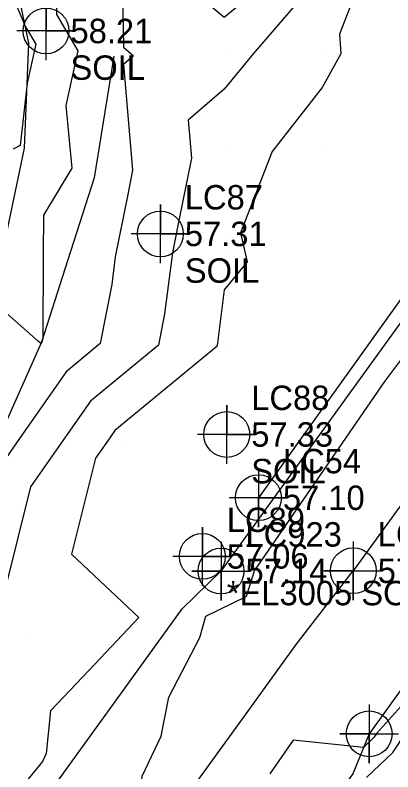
# Model space of a CAD drawing. Extents: x 2188792 to 2191981, y 386090 to 389710.
# Drawn here: x 2189598.9 to 2189637.5, y 386896.6 to 386974.1 of the extents above; entities that cross this region are included whole.
import ezdxf

# ---------------------------------------------------------------- set-up
doc = ezdxf.new("R2010")
doc.units = 0
for name, color, linetype in [('DTM Contours Major', 7, 'Continuous'), ('DTM Contours Minor', 7, 'Continuous'), ('Exist DTM QL2 LIDAR Elevation Point', 7, 'Continuous'), ('Exist Roads EOP', 7, 'Continuous'), ('Exist Roads EOP Cogo Elevation', 7, 'Continuous'), ('Exist Roads EOP Cogo Number', 7, 'Continuous'), ('Exist Roads EOP Cogo Point CELL', 7, 'Continuous'), ('Exist Roads EOT', 7, 'Continuous'), ('Exist Roads EOT Cogo Elevation', 7, 'Continuous'), ('Exist Roads EOT Cogo Number', 7, 'Continuous'), ('Exist Roads EOT Cogo Point CELL', 7, 'Continuous'), ('Exist Roads Soil Cogo Comment', 7, 'Continuous'), ('Exist Roads Soil Cogo Elevation', 7, 'Continuous'), ('Exist Roads Soil Cogo Number', 7, 'Continuous'), ('Exist Roads Soil Cogo Point CELL', 7, 'Continuous'), ('PH Exist DTM Breakline', 7, 'Continuous')]:
    doc.layers.add(name, color=color, linetype=linetype)

msp = doc.modelspace()

# ---------------------------------------------------------------- linework, layer by layer
at = {"layer": 'DTM Contours Major'}
for points in [[(2189634.793, 386896.032), (2189637.473, 386898.6), (2189638.925, 386900.819), (2189644.833, 386907.402), (2189646.214, 386909.493), (2189656.034, 386923.273), (2189657.363, 386925.28), (2189658.603, 386926.878), (2189659.963, 386928.63), (2189661.46, 386930.56), (2189674.176, 386948.424), (2189675.489, 386950.089), (2189676.955, 386951.946), (2189678.6, 386954.032), (2189687.057, 386966.203), (2189688.644, 386968.279), (2189690.321, 386970.473), (2189702.993, 386988.788)], [(2189598.458, 386976.342), (2189599.911, 386972.861), (2189600.962, 386971.086), (2189600.085, 386967.099), (2189599.372, 386960.714), (2189598.635, 386960.347)]]:
    msp.add_lwpolyline(points, dxfattribs=at)
at = {"layer": 'DTM Contours Minor'}
for points in [[(2189601.657, 387036.604), (2189618.405, 387013.751), (2189616.243, 386991.995), (2189616.527, 386990.987), (2189630.888, 386980.036), (2189630.229, 386978.331), (2189623.177, 386970.118), (2189620.228, 386966.506), (2189616.533, 386963.306), (2189616.87, 386959.434), (2189615.516, 386952.703), (2189614.928, 386949.749), (2189614.132, 386943.507), (2189613.507, 386940.291), (2189606.553, 386934.556), (2189603.995, 386930.889), (2189600.424, 386925.77), (2189597.718, 386914.935)], [(2189593.055, 387031.078), (2189600.943, 387033.286), (2189614.438, 387014.872), (2189612.991, 387000.305), (2189605.127, 386996.816), (2189608.731, 386989.594), (2189609.618, 386985.949), (2189609.81, 386978.627), (2189609.937, 386970.781), (2189610.963, 386969.912), (2189609.922, 386969.011), (2189610.862, 386958.212), (2189610.327, 386955.551), (2189609.091, 386949.344), (2189608.729, 386946.512), (2189607.551, 386940.447), (2189604.061, 386937.568), (2189599.768, 386931.415), (2189593.775, 386922.823)], [(2189594.519, 387001.065), (2189601.128, 386987.823), (2189602.944, 386980.358), (2189603.015, 386977.654), (2189603.072, 386974.14), (2189605.269, 386970.427), (2189604.037, 386964.824), (2189604.651, 386958.391), (2189601.761, 386953.606), (2189601.732, 386949.645), (2189601.666, 386940.969), (2189601.595, 386940.603), (2189601.568, 386940.581), (2189601.488, 386940.465), (2189601.205, 386940.706), (2189595.646, 386945.562)], [(2189616.322, 386990.396), (2189627.871, 386980.119), (2189620.228, 386973.839), (2189616.649, 386976.871), (2189616.604, 386979.6), (2189616.322, 386990.396)], [(2189634.896, 386979.534), (2189632.03, 386972.124), (2189632.158, 386970.118), (2189630.229, 386966.656), (2189625.118, 386960.117), (2189621.893, 386951.781), (2189622.589, 386948.802), (2189620.228, 386945.942), (2189619.534, 386940.501), (2189619.463, 386940.135), (2189609.045, 386931.544), (2189608.222, 386930.364), (2189607.073, 386928.716), (2189604.622, 386918.903), (2189611.512, 386912.406), (2189606.427, 386907.029), (2189602.475, 386902.85), (2189602.034, 386898.501), (2189601.65, 386897.677), (2189596.041, 386890.809)], [(2189595.706, 386865.733), (2189600.685, 386873.259), (2189600.927, 386873.579), (2189605.77, 386880.868), (2189606.162, 386881.389), (2189610.879, 386888.463), (2189611.275, 386889.439), (2189611.832, 386896.164), (2189613.77, 386900.277), (2189614.569, 386904.247), (2189617.719, 386910.372), (2189618.334, 386912.55), (2189622.467, 386914.577), (2189622.522, 386914.604), (2189623.321, 386917.175), (2189636.667, 386936.578), (2189639.311, 386940.124), (2189649.551, 386955.072), (2189652.538, 386959.069), (2189666.8, 386977.462)], [(2189690.18, 386977.049), (2189683.33, 386965.967), (2189675.62, 386954.246), (2189674.072, 386952.019), (2189674.041, 386951.979), (2189674.013, 386951.943), (2189673.988, 386951.911), (2189656.935, 386927.955), (2189656.782, 386927.758), (2189656.643, 386927.579), (2189656.516, 386927.415), (2189656.38, 386927.21), (2189643.714, 386909.437), (2189643.499, 386909.111), (2189635.829, 386900.566), (2189635.537, 386900.119), (2189634.487, 386899.114), (2189627.293, 386899.84), (2189624.901, 386896.425)]]:
    msp.add_lwpolyline(points, dxfattribs=at)
at = {"layer": 'Exist DTM QL2 LIDAR Elevation Point'}
for p, q in [((2189620.228, 386970.118), (2189620.228, 386970.118)), ((2189630.229, 386970.118), (2189630.229, 386970.118)), ((2189620.228, 386960.117), (2189620.228, 386960.117)), ((2189630.229, 386960.117), (2189630.229, 386960.117)), ((2189620.228, 386950.116), (2189620.228, 386950.116)), ((2189620.228, 386940.115), (2189620.228, 386940.115)), ((2189610.227, 386930.114), (2189610.227, 386930.114)), ((2189600.226, 386910.112), (2189600.226, 386910.112))]:
    msp.add_line(p, q, dxfattribs=at)
at = {"layer": 'Exist Roads EOP'}
msp.add_lwpolyline([(2190313.986, 387884.141), (2190285.547, 387843.636), (2190254.588, 387800.045), (2190225.155, 387759.32), (2190194.829, 387717.425), (2190164.291, 387675.101), (2190137.229, 387637.301), (2190105.098, 387592.774), (2190071.411, 387546.221), (2190039.296, 387501.568), (2190007.542, 387457.958), (2189976.844, 387415.407), (2189936.359, 387359.145), (2189907.138, 387318.716), (2189868.636, 387265.243), (2189836.428, 387220.463), (2189805.695, 387177.815), (2189775.592, 387135.957), (2189745.498, 387094.055), (2189715.496, 387052.249), (2189683.869, 387008.07), (2189653.218, 386965.867), (2189623.729, 386924.667)], dxfattribs=at)
at = {"layer": 'Exist Roads EOP Cogo Point CELL'}
msp.add_lwpolyline([(2189623.729, 386927.667), (2189623.729, 386921.667), (2189623.729, 386924.667), (2189626.729, 386924.667), (2189620.729, 386924.667)], dxfattribs=at)
msp.add_circle((2189623.729, 386924.667), 2.344, dxfattribs=at)
at = {"layer": 'Exist Roads EOT'}
for points in [[(2190174.375, 387667.889), (2190147.471, 387630.495), (2190115.247, 387585.778), (2190081.202, 387538.232), (2190049.502, 387494.256), (2190017.538, 387450.182), (2189987.334, 387408.357), (2189946.666, 387352.019), (2189917.402, 387311.129), (2189878.955, 387257.772), (2189846.565, 387212.819), (2189815.837, 387170.306), (2189785.374, 387128.351), (2189755.717, 387086.921), (2189724.953, 387044.041), (2189693.727, 387000.805), (2189663.933, 386959.217), (2189633.425, 386917.196)], [(2189989.253, 387391.986), (2189958.581, 387349.453), (2189928.09, 387307.216), (2189909.67, 387281.603), (2189884.44, 387246.513), (2189852.91, 387202.766), (2189821.507, 387159.305), (2189790.01, 387115.85), (2189759.16, 387072.957), (2189728.247, 387029.91), (2189696.407, 386985.689), (2189665.45, 386942.736), (2189635.049, 386900.502)], [(2189619.904, 386917.168), (2189650.19, 386959.038), (2189680.959, 387001.734), (2189713.171, 387046.57), (2189739.87, 387083.883), (2189771.556, 387127.847), (2189803.188, 387171.311), (2189835.065, 387215.496), (2189866.485, 387259.202), (2189892.308, 387295.019), (2189910.407, 387320.236), (2189942.075, 387364.22)]]:
    msp.add_lwpolyline(points, dxfattribs=at)
at = {"layer": 'Exist Roads EOT Cogo Point CELL'}
for points in [[(2189619.904, 386920.168), (2189619.904, 386914.168), (2189619.904, 386917.168), (2189616.904, 386917.168), (2189622.904, 386917.168)], [(2189633.425, 386920.196), (2189633.425, 386914.196), (2189633.425, 386917.196), (2189630.425, 386917.196), (2189636.425, 386917.196)], [(2189635.049, 386903.502), (2189635.049, 386897.502), (2189635.049, 386900.502), (2189632.049, 386900.502), (2189638.049, 386900.502)]]:
    msp.add_lwpolyline(points, dxfattribs=at)
for centre in [(2189619.904, 386917.168), (2189633.425, 386917.196), (2189635.049, 386900.502)]:
    msp.add_circle(centre, 2.344, dxfattribs=at)
at = {"layer": 'Exist Roads Soil Cogo Point CELL'}
for points in [[(2189602.01, 386969.445), (2189602.01, 386975.445), (2189602.01, 386972.445), (2189605.01, 386972.445), (2189599.01, 386972.445)], [(2189613.698, 386948.674), (2189613.698, 386954.674), (2189613.698, 386951.674), (2189616.698, 386951.674), (2189610.698, 386951.674)], [(2189620.492, 386928.147), (2189620.492, 386934.147), (2189620.492, 386931.147), (2189623.492, 386931.147), (2189617.492, 386931.147)], [(2189617.992, 386915.663), (2189617.992, 386921.663), (2189617.992, 386918.663), (2189620.992, 386918.663), (2189614.992, 386918.663)]]:
    msp.add_lwpolyline(points, dxfattribs=at)
for centre in [(2189602.01, 386972.445), (2189613.698, 386951.674), (2189620.492, 386931.147), (2189617.992, 386918.663)]:
    msp.add_circle(centre, 2.344, dxfattribs=at)
at = {"layer": 'PH Exist DTM Breakline'}
msp.add_line((2189615.936, 386913.305), (2189619.842, 386917.108), dxfattribs=at)
for points in [[(2189597.749, 386950.654), (2189599.806, 386960.464), (2189600.257, 386971.193), (2189599.036, 386977.084), (2189593.131, 386985.961)], [(2189608.93, 386969.867), (2189606.936, 386957.413), (2189604.242, 386949.008), (2189601.549, 386940.604), (2189597.597, 386931.685), (2189593.645, 386922.765), (2189589.452, 386915.915), (2189585.259, 386909.065), (2189581.066, 386902.215), (2189576.872, 386895.364), (2189571.293, 386887.108), (2189565.713, 386878.852), (2189560.134, 386870.597), (2189554.554, 386862.341), (2189548.975, 386854.085), (2189544.231, 386847.513), (2189539.488, 386840.942), (2189534.744, 386834.37)], [(2189568.47, 386827.629), (2189573.94, 386835.225), (2189579.409, 386842.822), (2189584.878, 386850.419), (2189590.347, 386858.016), (2189595.816, 386865.613), (2189601.285, 386873.21), (2189606.754, 386880.807), (2189612.224, 386888.404), (2189617.348, 386895.481), (2189622.472, 386902.557), (2189627.596, 386909.633), (2189633.425, 386917.196)], [(2189554.084, 386827.974), (2189558.22, 386833.622), (2189562.355, 386839.271), (2189566.491, 386844.919), (2189571.812, 386852.266), (2189577.132, 386859.614), (2189582.452, 386866.961), (2189587.772, 386874.308), (2189593.092, 386881.656), (2189598.413, 386889.003), (2189604.254, 386897.104), (2189610.095, 386905.204), (2189615.936, 386913.305)], [(2189635.049, 386900.502), (2189633.391, 386896.404), (2189627.898, 386888.863), (2189622.404, 386881.322), (2189617.087, 386873.856), (2189611.769, 386866.39), (2189606.452, 386858.924), (2189601.135, 386851.459), (2189595.817, 386843.993), (2189590.5, 386836.527), (2189585.183, 386829.061)]]:
    msp.add_lwpolyline(points, dxfattribs=at)

# ---------------------------------------------------------------- texts
at = {"layer": 'Exist Roads EOP Cogo Elevation'}
msp.add_text('57.10', height=2.5, dxfattribs=at).set_placement((2189626.229, 386923.417))
at = {"layer": 'Exist Roads EOP Cogo Number'}
msp.add_text('LC54', height=2.5, dxfattribs=at).set_placement((2189626.229, 386927.167))
at = {"layer": 'Exist Roads EOT Cogo Elevation'}
for s, p in [('57.14', (2189622.404, 386915.918)), ('57.37', (2189635.925, 386915.946))]:
    msp.add_text(s, height=2.5, dxfattribs=at).set_placement(p)
at = {"layer": 'Exist Roads EOT Cogo Number'}
for s, p in [('LC923', (2189622.404, 386919.668)), ('LC55', (2189635.925, 386919.696))]:
    msp.add_text(s, height=2.5, dxfattribs=at).set_placement(p)
at = {"layer": 'Exist Roads Soil Cogo Comment'}
for s, p in [('SOIL', (2189604.51, 386967.445)), ('SOIL', (2189616.198, 386946.674)), ('SOIL', (2189622.992, 386926.147)), ('*EL3005 SOIL', (2189620.492, 386913.663))]:
    msp.add_text(s, height=2.5, dxfattribs=at).set_placement(p)
at = {"layer": 'Exist Roads Soil Cogo Elevation'}
for s, p in [('58.21', (2189604.51, 386971.195)), ('57.31', (2189616.198, 386950.424)), ('57.33', (2189622.992, 386929.897)), ('57.06', (2189620.492, 386917.413))]:
    msp.add_text(s, height=2.5, dxfattribs=at).set_placement(p)
at = {"layer": 'Exist Roads Soil Cogo Number'}
for s, p in [('LC87', (2189616.198, 386954.174)), ('LC88', (2189622.992, 386933.647)), ('LC89', (2189620.492, 386921.163))]:
    msp.add_text(s, height=2.5, dxfattribs=at).set_placement(p)

doc.saveas('drawing.dxf')
